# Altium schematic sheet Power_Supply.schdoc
size 207 x 142 mm
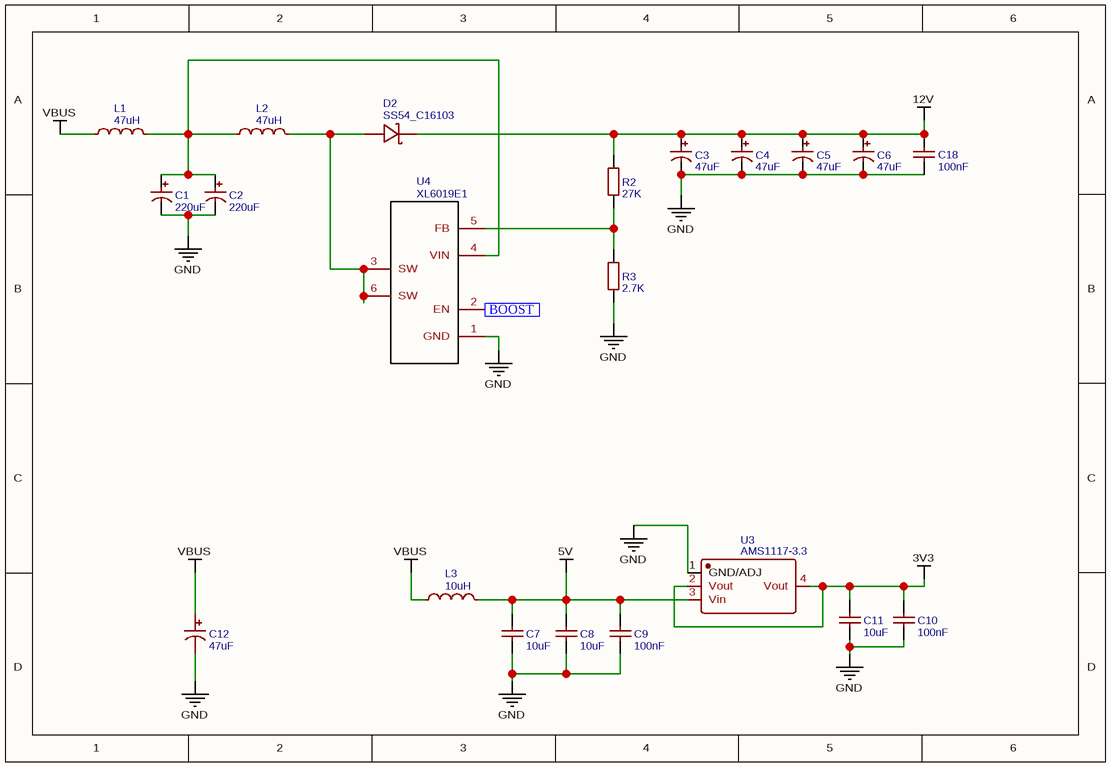
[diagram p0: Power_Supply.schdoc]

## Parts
C1  220uF  [CAP-SMD_BD6.3-L6.6-W6.6-RD]
C2  220uF  [CAP-SMD_BD6.3-L6.6-W6.6-RD]
C3  47uF  [CAP-SMD_BD6.3-L6.6-W6.6-FD]
C4  47uF  [CAP-SMD_BD6.3-L6.6-W6.6-FD]
C5  47uF  [CAP-SMD_BD6.3-L6.6-W6.6-FD]
C6  47uF  [CAP-SMD_BD6.3-L6.6-W6.6-FD]
C7  10uF  [C1206]
C8  10uF  [C1206]
C9  100nF  [C0805]
C10  100nF  [C0805]
C11  10uF  [C1206]
C12  47uF  [CAP-SMD_BD5.0-L5.3-W5.3-RD]
C18  100nF  [C0805]
D2  SS54_C16103  [SMC_L7.1-W6.2-LS8.1-R-RD]
L1  47uH  [IND-SMD_L10.5-W10.3_SLD10D50]
L2  47uH  [IND-SMD_L10.5-W10.3_SLD10D50]
L3  10uH  [L1206]
R2  27K  [R0805]
R3  2.7K  [R0805]
U3  AMS1117-3.3  [SOT-223-3_L6.5-W3.4-P2.30-LS7.0-BR]
U4  XL6019E1  [TO-263-5_L10.2-W9.9-P1.70-LS14.4-TL]

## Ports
BOOST (in)

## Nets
3V3: C10.2 C11.2 U3.2(Vout) U3.4(Vout)
5V: C7.2 C8.2 C9.2 L3.2 U3.3(Vin)
12V: C3.1 C4.1 C5.1 C6.1 C18.2 D2.2(K) R2.2
GND: C1.2 C2.2 C3.2 C4.2 C5.2 C6.2 C7.1 C8.1 C9.1 C10.1 C11.1 C12.2 C18.1 R3.2 U3.1(GND/ADJ) U4.1(GND)
VBUS: C12.1 L1.1 L3.1
BOOST: U4.2(EN) ; port BOOST
NetC1_1: C1.1 C2.1 L1.2 L2.1 U4.4(VIN)
NetD2_1: D2.1(A) L2.2 U4.3(SW) U4.6(SW)
NetR2_1: R2.1 R3.1 U4.5(FB)

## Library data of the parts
C1 C2 = 220uF: BOM_Manufacturer: HONOR; BOM_Manufacturer Part: RVT1A221M0605; nameAlias: Capacitance
C3-C6 = 47uF: BOM_Manufacturer: ROQANG; BOM_Manufacturer Part: RVE1V470M0605; nameAlias: Capacitance; BOM_Paste Type: Extended Part
C7 C8 C11 = 10uF: BOM_Manufacturer Part: CL31A106KBHNNNE; BOM_Manufacturer: SAMSUNG; nameAlias: Capacitance
C9 C10 C18 = 100nF: BOM_Manufacturer Part: CC0805KRX7R9BB104; BOM_Manufacturer: YAGEO; nameAlias: Capacitance
C12 = 47uF: BOM_Manufacturer: SEMTECH; BOM_Manufacturer Part: CS1C470M-CRD54; nameAlias: Capacitance
D2 = SS54_C16103: BOM_Manufacturer Part: SS54; BOM_Manufacturer: MDD
L1 L2 = 47uH: BOM_Manufacturer: Sunltech Tech; BOM_Manufacturer Part: SLD10D50S470MTT; nameAlias: Inductance; Contributor: LCSC
L3 = 10uH: BOM_Manufacturer Part: CMI321609X100KT; BOM_Manufacturer: FH; nameAlias: Inductance
R2 = 27K: BOM_Manufacturer: UniOhm; BOM_Manufacturer Part: 0805W8F2702T5E; nameAlias: Resistance (Ohms)
R3 = 2.7K: BOM_Manufacturer: UniOhm; BOM_Manufacturer Part: 0805W8F2701T5E; nameAlias: Resistance (Ohms)
U3 = AMS1117-3.3: BOM_Manufacturer: AMS; sourceId: dwIGgezVh
U4 = XL6019E1: BOM_Manufacturer: XLSEMI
